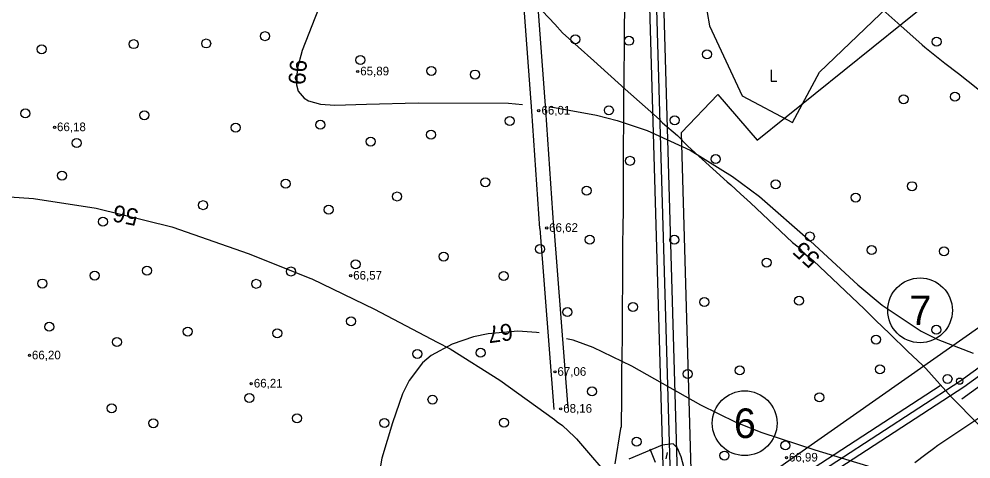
# Model space of a CAD drawing. Extents: x 532503 to 539665, y 6557663 to 6561526.
# Drawn here: x 534790.2 to 535060.8, y 6559862.6 to 6559987.5 of the extents above; entities that cross this region are included whole.
import ezdxf

# ---------------------------------------------------------------- set-up
doc = ezdxf.new("R2010")
doc.units = 0
for name, color, linetype in [('Default', 7, 'Continuous'), ('HALJASTUS', 7, 'Continuous'), ('HORISONTAAL-EH2000', 7, 'Continuous'), ('illumineerimisjooned', 7, 'Continuous'), ('Kaitsevöönd', 7, 'Continuous'), ('KORGUS-EH2000', 7, 'Continuous'), ('Lamami horisontaal_EH2000', 7, 'Continuous'), ('PIIR', 7, 'Continuous'), ('PIIR_me', 7, 'Continuous'), ('Plokid', 7, 'Continuous'), ('RELJEEF', 7, 'Continuous'), ('TEE', 7, 'Continuous')]:
    doc.layers.add(name, color=color, linetype=linetype)

# ---------------------------------------------------------------- blocks, each defined once
blk = doc.blocks.new('RAIESM')
at = {"layer": 'Default'}
for points in [[(0, 2), (0, 0)], [(0, 0), (1, 0)]]:
    blk.add_lwpolyline(points, dxfattribs=at)
blk = doc.blocks.new('METS')
at = {"layer": 'HALJASTUS'}
blk.add_circle((0, 0), 0.8, dxfattribs=at)

msp = doc.modelspace()

# ---------------------------------------------------------------- linework, layer by layer
at = {"layer": 'HALJASTUS'}
msp.add_lwpolyline([(534981.15, 6560048.47), (534981.15, 6560015.98), (534986.41, 6559985.59), (534995.76, 6559965.71), (535010.08, 6559958.11), (535017.67, 6559972.43), (535045.72, 6559999.32), (535085.45, 6560021.24), (535129.56, 6560033.23), (535154.39, 6560025.04), (535177.18, 6560027.09), (535199.97, 6560029.13), (535208.15, 6560023.87), (535213.7, 6560013.94), (535214.01, 6560004.82)], dxfattribs=at)
at = {"layer": 'HORISONTAAL-EH2000'}
for points in [[(534884.49, 6560036.9), (534884.51, 6560034.95), (534882.82, 6560021.4), (534880.76, 6560006.72), (534878.73, 6559999.15), (534875.31, 6559990.41), (534870.64, 6559978.59), (534869.24, 6559973.32), (534869.06, 6559968.89), (534869.56, 6559967.09), (534871.21, 6559965.03), (534872.5, 6559964.29), (534875.87, 6559963.39), (534879.97, 6559963.08), (534888.92, 6559963.32), (534903.62, 6559963.72), (534929.34, 6559963.61), (534933.3, 6559963.26)], [(534940.74, 6559962.6), (534942.41, 6559962.45), (534954.33, 6559960.25), (534960.16, 6559958.72), (534968.71, 6559955.86), (534980.94, 6559950.31), (534993.02, 6559942.83), (535000.63, 6559937.1), (535015.15, 6559924.48), (535028.58, 6559912.1), (535035.52, 6559906.32), (535046.62, 6559898.9), (535051.37, 6559896.5), (535061.38, 6559892.69)], [(534938, 6559898.41), (534937.27, 6559898.56), (534931.96, 6559898.88), (534923.55, 6559898.18), (534919.4, 6559897.27), (534913.34, 6559895.19), (534907.37, 6559891.99), (534904.82, 6559889.89), (534901.08, 6559884.92), (534899.23, 6559881.08), (534896.31, 6559872.84), (534893.27, 6559862.83), (534892.41, 6559857.8), (534892.2, 6559849.48), (534891.43, 6559838.68), (534883.27, 6559830.1), (534876.74, 6559823.42), (534874.42, 6559818.77), (534875.15, 6559815.87), (534879.5, 6559815.58), (534883.86, 6559814.27), (534884.87, 6559810.2), (534882.55, 6559805.27), (534880.83, 6559803.55)], [(535072.08, 6559852.43), (535042.23, 6559857.77), (535033.58, 6559859.93), (535016.45, 6559865.1), (535001.38, 6559870.04), (534994.05, 6559872.95), (534983.99, 6559877.9), (534964.33, 6559888.98), (534953.38, 6559894.3), (534947.66, 6559896.37), (534945.79, 6559896.76)]]:
    msp.add_lwpolyline(points, dxfattribs=at)
at = {"layer": 'illumineerimisjooned'}
msp.add_lwpolyline([(534967.67, 6560049.69), (534974.15, 6559828.08), (535058.69, 6559883.05), (535223.5, 6560002.45), (535218.56, 6560049.92), (535415.93, 6559990.42), (535455.45, 6559927.19), (535490.31, 6559867.16), (535479.12, 6559828.38), (535249.57, 6559653.05), (535182.36, 6559690.84), (534940.99, 6559819.22), (534872.14, 6559776.44), (534954.37, 6559534.34), (534950.91, 6559533.67), (534733.22, 6559487.12), (534375.58, 6559465.86), (534199.95, 6559448.92), (533951.79, 6559660.13), (534200.21, 6559977.65), (534931.63, 6560046.31)], close=True, dxfattribs=at)
at = {"layer": 'Kaitsevöönd'}
msp.add_lwpolyline([(535000, 6559953.12), (535049.42, 6559992.99), (535086.86, 6560014.83), (535132.35, 6560020.86), (535156.39, 6560022.14), (535166.68, 6560016.65), (535179.42, 6560020.55), (535204.9, 6560018.21), (535209.94, 6560002.96), (535206.22, 6560000.36), (534981.72, 6559843), (534978.44, 6559955.29), (534988.83, 6559966.07)], close=True, dxfattribs=at)
at = {"layer": 'KORGUS-EH2000'}
for centre in [(534886.47, 6559972.64), (534937.92, 6559961.51), (534800.29, 6559956.79), (534940.17, 6559928.2), (534884.47, 6559914.64), (534793.16, 6559892), (534942.52, 6559887.34), (534856.16, 6559884), (534944.17, 6559876.84), (535008.32, 6559862.98)]:
    msp.add_circle(centre, 0.32, dxfattribs=at)
at = {"layer": 'Lamami horisontaal_EH2000'}
for points in [[(534978.38, 6560052.7), (534981.25, 6560049.4), (534987.29, 6560042.26), (534995.14, 6560033.31), (534998.05, 6560029.43), (535002.24, 6560024.64), (535002.32, 6560024.55), (535012.03, 6560014.17), (535015.2, 6560010.39), (535018.42, 6560007.03), (535029.1, 6559996.56), (535029.84, 6559995.79), (535033.37, 6559992.5), (535036.53, 6559989.41), (535040.79, 6559985.64)], [(534924.69, 6560004.93), (534942.48, 6559986.12), (534944.69, 6559983.6), (534953.53, 6559975.66), (534962.5, 6559967.58), (534972.23, 6559958.99), (534973.13, 6559958.04), (534977.31, 6559954.42), (534980.32, 6559951.47), (534991.49, 6559941.35), (534992.48, 6559940.43), (534995.21, 6559937.9), (534998.13, 6559935.32), (535010.02, 6559924.09), (535011.61, 6559922.81), (535013.62, 6559920.77), (535015.95, 6559918.93), (535030.52, 6559905.19), (535033.76, 6559901.92), (535037.59, 6559898.24)], [(535040.79, 6559985.64), (535046.9, 6559980.23), (535047.66, 6559979.57), (535053.31, 6559975.01), (535057.23, 6559972.05), (535065.47, 6559965.51), (535065.91, 6559965.24), (535076.27, 6559958.04), (535083.28, 6559953.53), (535101.1, 6559943.46), (535106.56, 6559940.73), (535118.91, 6559935.06), (535123.71, 6559932.63)], [(534776.53, 6559937.84), (534794.34, 6559936.54), (534812.15, 6559933.83), (534833.64, 6559928.51), (534833.89, 6559928.42), (534855.33, 6559920.99), (534855.62, 6559920.83), (534872.81, 6559913.99), (534873.43, 6559913.78), (534891.25, 6559905.16), (534909.06, 6559895.8), (534912.7, 6559893.87), (534926.88, 6559885.01), (534942.41, 6559873.82), (534943.18, 6559873.11), (534944.69, 6559872.08), (534948.04, 6559868.91), (534948.61, 6559868.34), (534959.56, 6559855.63)], [(535037.59, 6559898.24), (535042.8, 6559893.1), (535046.98, 6559889.23)], [(535046.98, 6559889.23), (535047.92, 6559888.34), (535055.19, 6559880.2), (535062.79, 6559872.51)]]:
    msp.add_lwpolyline(points, dxfattribs=at)
at = {"layer": 'PIIR'}
for centre, radius in [((535046.29, 6559904.81), 9.2), ((535057.56, 6559884.7), 0.88), ((535057.56, 6559884.7), 0.88), ((534996.44, 6559872.76), 9.2)]:
    msp.add_circle(centre, radius, dxfattribs=at)
at = {"layer": 'PIIR_me'}
msp.add_lwpolyline([(534441.63, 6560002.32), (534688.17, 6560025.46), (534931.44, 6560048.3), (534969.61, 6560051.88), (534976.05, 6559831.7), (535057.56, 6559884.7), (535221.39, 6560003.39), (535216.26, 6560052.7), (535417.23, 6559992.12), (535457.16, 6559928.22), (535492.47, 6559867.43), (535480.86, 6559827.19), (535250.12, 6559650.95), (535250.12, 6559650.95), (535181.4, 6559689.09), (534941.07, 6559816.91), (534874.54, 6559775.58), (534957, 6559532.81), (534951.31, 6559531.71), (534733.49, 6559485.13), (534485.11, 6559470.37)], dxfattribs=at)
at = {"layer": 'Plokid'}
for points in [[(534971.81, 6560045.13), (534977.95, 6559835.31), (535052.03, 6559883.49)], [(535058.12, 6559879.67), (535226.03, 6560001.32), (535221.59, 6560043.99)], [(534962.26, 6559994.98), (534962.14, 6559980.42), (534962.08, 6559970.76), (534962.04, 6559965.01), (534961.93, 6559944.48), (534961.92, 6559942.98), (534961.88, 6559936.73), (534961.86, 6559935), (534961.86, 6559931.97), (534961.82, 6559929.75), (534961.75, 6559922.39), (534961.73, 6559918.95), (534961.69, 6559913.24), (534961.67, 6559910.81), (534961.66, 6559907.6), (534961.6, 6559901.86), (534961.58, 6559895.39), (534961.56, 6559893.66), (534961.46, 6559885.48), (534961.43, 6559880.15), (534961.29, 6559871.76), (534961.13, 6559871.27), (534959.57, 6559861.25)], [(535044.78, 6559861.59), (535047.95, 6559863.94), (535050.1, 6559865.58), (535051.31, 6559866.5), (535057.85, 6559870.84), (535064.17, 6559875.02)]]:
    msp.add_lwpolyline(points, dxfattribs=at)
at = {"layer": 'RELJEEF'}
for p, q in [((534971.1, 6559861.6), (534969.57, 6559865.37)), ((534974.43, 6559864.43), (534974.07, 6559862.61))]:
    msp.add_line(p, q, dxfattribs=at)
msp.add_lwpolyline([(534981.41, 6559851.84), (534978.36, 6559863.2), (534977.38, 6559865.65), (534976.15, 6559866.91), (534973, 6559866.54), (534963.5, 6559862.54)], dxfattribs=at)
at = {"layer": 'TEE'}
for p, q in [((534935.93, 6559961.37), (534933.68, 6559991.85)), ((534939.92, 6559961.66), (534937.67, 6559992.14)), ((534938.17, 6559928.07), (534935.93, 6559961.38)), ((534942.16, 6559928.34), (534939.92, 6559961.65)), ((534938.17, 6559928.05), (534942.18, 6559876.68)), ((534942.16, 6559928.36), (534946.17, 6559876.99))]:
    msp.add_line(p, q, dxfattribs=at)

# ---------------------------------------------------------------- block references
at = {"layer": 'HALJASTUS', "xscale": 1.6, "yscale": 1.6000000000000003}
for name, p in [('METS', (534822.79, 6559980.4)), ('METS', (534843.38, 6559980.59)), ('METS', (534860.08, 6559982.67)), ('METS', (534948.31, 6559981.76)), ('METS', (534963.52, 6559981.35)), ('METS', (535050.98, 6559981.09)), ('METS', (534796.6, 6559978.94)), ('METS', (534985.73, 6559977.52)), ('METS', (534887.23, 6559975.88)), ('METS', (534907.36, 6559972.81)), ('METS', (534919.8, 6559971.78)), ('RAIESM', (535004.01, 6559969.89)), ('METS', (535041.6, 6559964.76)), ('METS', (535056.19, 6559965.47)), ('METS', (534957.83, 6559961.63)), ('METS', (534792, 6559960.72)), ('METS', (534825.82, 6559960.23)), ('METS', (534929.68, 6559958.6)), ('METS', (534976.53, 6559958.79)), ('METS', (534851.74, 6559956.71)), ('METS', (534875.83, 6559957.51)), ('METS', (534907.3, 6559954.69)), ('METS', (534806.57, 6559952.31)), ('METS', (534890.13, 6559952.74)), ('METS', (534988.2, 6559947.75)), ('METS', (534963.84, 6559947.27)), ('METS', (534802.4, 6559943.09)), ('METS', (534865.98, 6559940.77)), ('METS', (534922.75, 6559941.2)), ('METS', (535005.23, 6559940.6)), ('METS', (535044, 6559940.07)), ('METS', (534897.65, 6559937.14)), ('METS', (534951.49, 6559938.82)), ('METS', (535027.97, 6559936.84)), ('METS', (534842.51, 6559934.68)), ('METS', (534878.18, 6559933.38)), ('METS', (534814.02, 6559929.98)), ('METS', (534952.41, 6559924.86)), ('METS', (534976.47, 6559924.85)), ('METS', (535014.96, 6559925.78)), ('METS', (534938.25, 6559922.21)), ('METS', (535032.5, 6559921.92)), ('METS', (535053.1, 6559921.58)), ('METS', (534885.83, 6559917.9)), ('METS', (534910.87, 6559920.09)), ('METS', (535002.66, 6559918.38)), ('METS', (534826.54, 6559916.08)), ('METS', (534867.49, 6559915.84)), ('METS', (534796.83, 6559912.43)), ('METS', (534811.67, 6559914.69)), ('METS', (534927.97, 6559914.55)), ('METS', (534857.6, 6559912.34)), ('METS', (534984.95, 6559907.17)), ('METS', (535011.92, 6559907.53)), ('METS', (534946.06, 6559904.31)), ('METS', (534964.69, 6559905.77)), ('METS', (534884.57, 6559901.7)), ('METS', (534798.76, 6559900.15)), ('METS', (535050.93, 6559899.29)), ('METS', (534838.16, 6559898.79)), ('METS', (534863.58, 6559898.3)), ('METS', (535033.79, 6559896.51)), ('METS', (534818, 6559895.8)), ('METS', (534903.39, 6559892.44)), ('METS', (534921.37, 6559892.76)), ('METS', (535034.87, 6559888.08)), ('METS', (534980.27, 6559886.74)), ('METS', (534995.05, 6559887.74)), ('METS', (535054.09, 6559885.34)), ('METS', (534953.05, 6559881.78)), ('METS', (535017.7, 6559880.09)), ('METS', (534855.63, 6559879.92)), ('METS', (534907.71, 6559879.48)), ('METS', (534816.5, 6559876.99)), ('METS', (534828.35, 6559872.76)), ('METS', (534869.22, 6559874.15)), ('METS', (534894.05, 6559872.84)), ('METS', (534928.01, 6559872.93)), ('METS', (534965.7, 6559867.5)), ('METS', (535008.03, 6559866.44)), ('METS', (534990.7, 6559863.57))]:
    msp.add_blockref(name, p, dxfattribs=at)

# ---------------------------------------------------------------- texts
at = {"layer": 'HORISONTAAL-EH2000'}
for s, rotation, p in [('66', 85.0581, (534871.48, 6559968.68)), ('67', 188.0711, (534930.16, 6559901.2))]:
    msp.add_text(s, height=4.8, rotation=rotation, dxfattribs=at).set_placement(p)
at = {"layer": 'KORGUS-EH2000'}
for s, p in [('65,89', (534887.17, 6559971.54)), ('66,01', (534938.69, 6559960.41)), ('66,18', (534800.98, 6559955.69)), ('66,62', (534940.86, 6559927.1)), ('66,57', (534885.17, 6559913.54)), ('66,20', (534793.85, 6559890.9)), ('67,06', (534943.21, 6559886.23)), ('66,21', (534856.92, 6559882.9)), ('68,16', (534944.87, 6559875.74)), ('66,99', (535009.02, 6559861.88))]:
    msp.add_text(s, height=2.45, dxfattribs=at).set_placement(p)
at = {"layer": 'Lamami horisontaal_EH2000'}
for s, rotation, p in [('56', 168.5294, (534824.43, 6559933.42)), ('55', 137.8835, (535018.22, 6559919.95))]:
    msp.add_text(s, height=4.8, rotation=rotation, dxfattribs=at).set_placement(p)
at = {"layer": 'PIIR'}
for s, p in [('7', (535043.28, 6559900.61)), ('6', (534993.38, 6559868.56))]:
    msp.add_text(s, height=8.4, dxfattribs=at).set_placement(p)

doc.saveas('drawing.dxf')
